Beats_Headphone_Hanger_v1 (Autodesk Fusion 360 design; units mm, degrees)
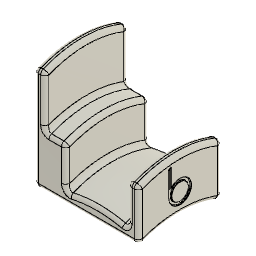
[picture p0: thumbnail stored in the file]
part number: v01
sketch "Sketch2" plane through (0, 0, 0) normal (0, 1, 0) x axis (1, 0, 0)
  line L1 (50, 0) -> (0, 0)
  line L2 (50, -25) -> (50, 0)
  line L3 (45, -25) -> (50, -25)
  line L4 (45, -5) -> (45, -25)
  line L5 (15, -25) -> (15, -5)
  line L6 (5, -25) -> (15, -25)
  line L7 (5, -50) -> (5, -25)
  line L8 (0, -50) -> (5, -50)
  line L9 (0, 0) -> (0, -50)
  arc A1 centre (30, 48.2353) radius 55.3082 clockwise from (45, -5) to (15, -5)
  point P1 (0, 0)
  point P2 (0, 0)
  point P12 (0, 0)
  point P3 (50, 0)
  point P4 (50, -25)
  point P5 (45, -25)
  point P6 (45, -5)
  point P7 (15, -5)
  point P8 (15, -25)
  point P9 (5, -25)
  coincident P1 P2
  horizontal L1
  perpendicular L1 L2
  perpendicular L2 L3
  perpendicular L3 L4
  perpendicular L5 L6
  perpendicular L6 L7
  perpendicular L5 L8
  coincident P1 P12
  perpendicular L1 L9
  dimension "d1" distance P3 P4 = 25
  dimension "d2" distance P4 P5 = 5
  dimension "d3" distance P5 P6 = 20
  dimension "d4" distance P6 P7 = 30
  dimension "d5" distance P8 P9 = 10
sketch "Sketch5" plane through (0, 0, 0) normal (1, 0, 0) x axis (0, 1, 0)
  arc A1 centre (20, -45.8575) radius 50.0291 clockwise from (0, 0) to (40, 0)
  point P1 (0, 0)
  point P2 (0, 0)
  point P3 (40, 0)
  coincident P1 P2
  dimension "d8" distance P2 P3 = 40
sweep "Sweep1" sketch "Sketch2" TwistAngle 0 TaperAngle 0
fillet "Fillet1" radius 2
sketch "Sketch6" plane through (50, 0, 0) normal (1, 0, 0) x axis (0, 1, 0)
  line L1 (2, 2.9588) -> (2, 23.6711)
  line L2 (38, 23.6711) -> (38, 2.9588)
  line L3 (14.5658, 25.1409) -> (14.5658, 13.6025)
  line L4 (15.7685, 25.9789) -> (14.5658, 25.1409)
  line L5 (15.7685, 17.0318) -> (15.7685, 25.9789)
  arc A1 centre (20, -45.8575) radius 52.0291 clockwise from (2, 2.9588) to (38, 2.9588)
  arc A2 centre (20, -20.8575) radius 48.0291 clockwise from (2, 23.6711) to (38, 23.6711)
  circle C1 centre (20.0559, 13.6025) radius 4
  circle C2 centre (20.0559, 13.6025) radius 5.4901
  point P10 (14.5658, 13.6025)
  point P13 (15.7685, 17.0318)
  concentric C1 C2
  coincident C2 P10
  tangent C2 L3
  vertical L3
  coincident C2 P13
  parallel L3 L5
  dimension "d16" diameter C1 = 8
extrude "Extrude1" cut sketch "Sketch6" profile of C1 C2 L3 L4 L5 against normal blind 0.5
fillet "Fillet2" radius 0.25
